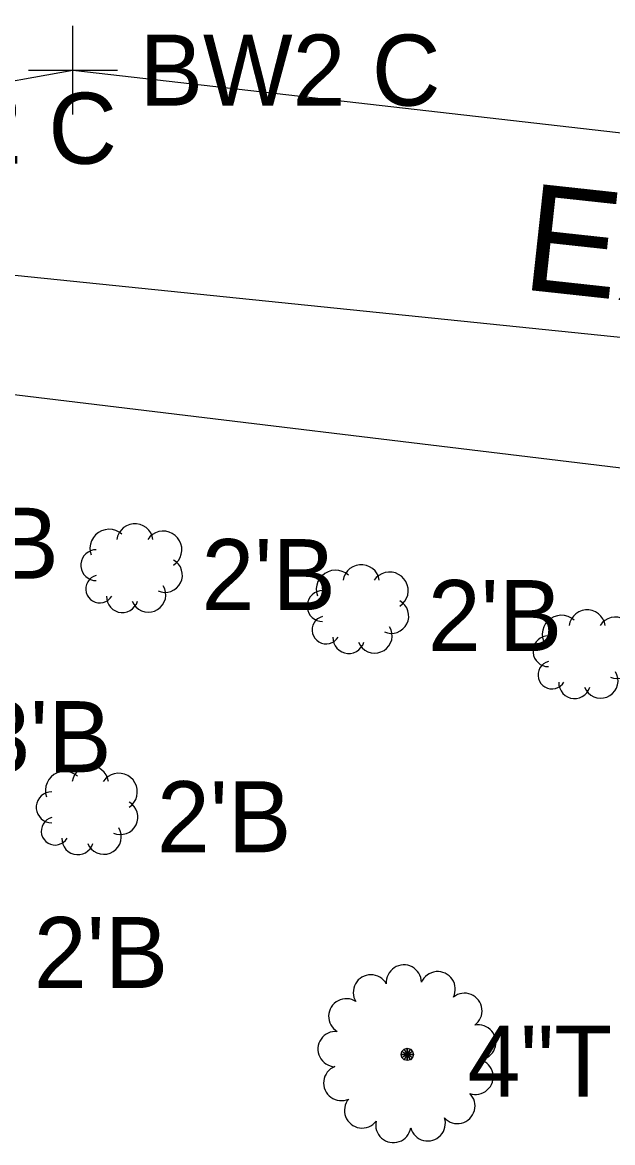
# Model space of a CAD drawing. Extents: x 1363693 to 1365209, y 422201 to 424153.
# Drawn here: x 1364123.23 to 1364136.52, y 423073.16 to 423098.38 of the extents above; entities that cross this region are included whole.
import ezdxf

# ---------------------------------------------------------------- set-up
doc = ezdxf.new("R2010")
doc.units = 0
for name, color, linetype in [('O-ALGN-TEXT-BASELINE-WERK-CL-RW', 7, 'Continuous'), ('SV_X_Shot_Marker', 7, 'Continuous'), ('UT_X_Electric', 7, 'Continuous'), ('UT_X_Electric_Text', 7, 'Continuous'), ('VG_X_Cells', 7, 'Continuous'), ('VG_X_Flower_Bed', 7, 'Continuous'), ('VG_X_Text', 7, 'Continuous')]:
    doc.layers.add(name, color=color, linetype=linetype)

msp = doc.modelspace()

# ---------------------------------------------------------------- linework, layer by layer
at = {"layer": 'O-ALGN-TEXT-BASELINE-WERK-CL-RW'}
msp.add_lwpolyline([(1364082.455, 423089.956), (1364091.492, 423091.463), (1364096.033, 423092.212), (1364096.16, 423092.322), (1364105.9, 423094.014), (1364117.087, 423095.993), (1364124.372, 423097.302), (1364141.98, 423095.292), (1364166.947, 423092.589), (1364178.078, 423091.327), (1364181.068, 423090.938), (1364184.015, 423090.305), (1364184.015, 423090.305), (1364187.51, 423089.214), (1364190.879, 423087.78), (1364190.879, 423087.78), (1364196.807, 423084.458), (1364200.629, 423083.854), (1364205.148, 423082.949)], dxfattribs=at)
at = {"layer": 'SV_X_Shot_Marker'}
for p, q in [((1364124.372, 423096.302), (1364124.372, 423098.302)), ((1364123.372, 423097.302), (1364125.372, 423097.302))]:
    msp.add_line(p, q, dxfattribs=at)
at = {"layer": 'UT_X_Electric'}
msp.add_lwpolyline([(1364201.55, 423074.962), (1364187.938, 423086.039), (1364061.994, 423098.936)], dxfattribs=at)
at = {"layer": 'VG_X_Cells'}
for points in [[(1364125.476, 423086.853), (1364125.411, 423086.902), (1364125.338, 423086.937), (1364125.259, 423086.959), (1364125.177, 423086.965), (1364125.096, 423086.955), (1364125.018, 423086.931), (1364124.947, 423086.892), (1364124.883, 423086.841), (1364124.831, 423086.778), (1364124.791, 423086.707), (1364124.765, 423086.63), (1364124.755, 423086.549), (1364124.76, 423086.467), (1364124.78, 423086.388)], [(1364126.173, 423086.737), (1364126.154, 423086.812), (1364126.122, 423086.883), (1364126.077, 423086.947), (1364126.02, 423087.001), (1364125.955, 423087.043), (1364125.882, 423087.072), (1364125.806, 423087.087), (1364125.727, 423087.087), (1364125.651, 423087.072), (1364125.578, 423087.043), (1364125.513, 423087.001), (1364125.456, 423086.947), (1364125.411, 423086.883), (1364125.378, 423086.812), (1364125.36, 423086.737)], [(1364126.637, 423086.156), (1364126.698, 423086.205), (1364126.748, 423086.264), (1364126.787, 423086.332), (1364126.812, 423086.406), (1364126.823, 423086.482), (1364126.82, 423086.56), (1364126.802, 423086.636), (1364126.771, 423086.707), (1364126.727, 423086.772), (1364126.672, 423086.827), (1364126.608, 423086.87), (1364126.537, 423086.902), (1364126.461, 423086.919), (1364126.383, 423086.922), (1364126.306, 423086.911), (1364126.233, 423086.886), (1364126.165, 423086.847), (1364126.106, 423086.797), (1364126.057, 423086.737)], [(1364124.896, 423086.504), (1364124.832, 423086.498), (1364124.77, 423086.481), (1364124.712, 423086.452), (1364124.661, 423086.413), (1364124.618, 423086.366), (1364124.584, 423086.311), (1364124.561, 423086.251), (1364124.549, 423086.188), (1364124.549, 423086.124), (1364124.561, 423086.061), (1364124.584, 423086.001), (1364124.618, 423085.946), (1364124.661, 423085.899), (1364124.712, 423085.86), (1364124.77, 423085.831), (1364124.832, 423085.814), (1364124.896, 423085.808)], [(1364126.289, 423085.575), (1364126.359, 423085.552), (1364126.433, 423085.542), (1364126.507, 423085.547), (1364126.579, 423085.565), (1364126.646, 423085.597), (1364126.705, 423085.641), (1364126.756, 423085.695), (1364126.795, 423085.758), (1364126.822, 423085.827), (1364126.835, 423085.9), (1364126.834, 423085.974), (1364126.819, 423086.047), (1364126.791, 423086.115), (1364126.75, 423086.177), (1364126.698, 423086.23), (1364126.637, 423086.272)], [(1364131.27, 423085.815), (1364131.251, 423085.89), (1364131.219, 423085.961), (1364131.174, 423086.025), (1364131.117, 423086.079), (1364131.052, 423086.121), (1364130.979, 423086.15), (1364130.903, 423086.165), (1364130.824, 423086.165), (1364130.748, 423086.15), (1364130.675, 423086.121), (1364130.61, 423086.079), (1364130.553, 423086.025), (1364130.508, 423085.961), (1364130.475, 423085.89), (1364130.457, 423085.815)], [(1364124.896, 423085.924), (1364124.838, 423085.903), (1364124.785, 423085.871), (1364124.74, 423085.829), (1364124.704, 423085.779), (1364124.678, 423085.724), (1364124.663, 423085.664), (1364124.661, 423085.603), (1364124.67, 423085.542), (1364124.691, 423085.484), (1364124.723, 423085.432), (1364124.765, 423085.386), (1364124.814, 423085.35), (1364124.87, 423085.324), (1364124.93, 423085.309), (1364124.991, 423085.306), (1364125.052, 423085.316), (1364125.11, 423085.337), (1364125.162, 423085.368), (1364125.208, 423085.41), (1364125.244, 423085.459)], [(1364130.573, 423085.931), (1364130.508, 423085.98), (1364130.435, 423086.015), (1364130.356, 423086.037), (1364130.274, 423086.043), (1364130.193, 423086.033), (1364130.115, 423086.009), (1364130.044, 423085.97), (1364129.98, 423085.919), (1364129.928, 423085.856), (1364129.888, 423085.785), (1364129.862, 423085.708), (1364129.852, 423085.627), (1364129.857, 423085.545), (1364129.877, 423085.466)], [(1364131.734, 423085.234), (1364131.795, 423085.283), (1364131.845, 423085.342), (1364131.884, 423085.41), (1364131.909, 423085.484), (1364131.92, 423085.56), (1364131.917, 423085.638), (1364131.899, 423085.714), (1364131.868, 423085.785), (1364131.824, 423085.85), (1364131.769, 423085.905), (1364131.705, 423085.948), (1364131.634, 423085.98), (1364131.558, 423085.997), (1364131.48, 423086), (1364131.403, 423085.989), (1364131.33, 423085.964), (1364131.262, 423085.925), (1364131.203, 423085.875), (1364131.154, 423085.815)], [(1364125.708, 423085.343), (1364125.743, 423085.276), (1364125.791, 423085.216), (1364125.848, 423085.167), (1364125.915, 423085.13), (1364125.987, 423085.107), (1364126.062, 423085.098), (1364126.138, 423085.103), (1364126.211, 423085.124), (1364126.279, 423085.157), (1364126.339, 423085.204), (1364126.389, 423085.261), (1364126.427, 423085.327), (1364126.452, 423085.399), (1364126.462, 423085.474), (1364126.457, 423085.55), (1364126.438, 423085.623), (1364126.405, 423085.692)], [(1364125.128, 423085.459), (1364125.132, 423085.391), (1364125.149, 423085.325), (1364125.178, 423085.263), (1364125.218, 423085.207), (1364125.269, 423085.161), (1364125.327, 423085.125), (1364125.391, 423085.101), (1364125.459, 423085.09), (1364125.528, 423085.092), (1364125.594, 423085.107), (1364125.657, 423085.134), (1364125.713, 423085.173), (1364125.761, 423085.222), (1364125.799, 423085.28), (1364125.825, 423085.343)], [(1364129.993, 423085.582), (1364129.929, 423085.576), (1364129.867, 423085.559), (1364129.809, 423085.53), (1364129.758, 423085.491), (1364129.715, 423085.444), (1364129.681, 423085.389), (1364129.658, 423085.329), (1364129.646, 423085.266), (1364129.646, 423085.202), (1364129.658, 423085.139), (1364129.681, 423085.079), (1364129.715, 423085.024), (1364129.758, 423084.977), (1364129.809, 423084.938), (1364129.867, 423084.909), (1364129.929, 423084.892), (1364129.993, 423084.886)], [(1364131.386, 423084.653), (1364131.456, 423084.63), (1364131.53, 423084.62), (1364131.604, 423084.625), (1364131.676, 423084.643), (1364131.743, 423084.675), (1364131.802, 423084.719), (1364131.853, 423084.773), (1364131.892, 423084.836), (1364131.919, 423084.905), (1364131.932, 423084.978), (1364131.931, 423085.052), (1364131.916, 423085.125), (1364131.888, 423085.193), (1364131.847, 423085.255), (1364131.795, 423085.308), (1364131.734, 423085.35)], [(1364136.357, 423084.8), (1364136.338, 423084.875), (1364136.306, 423084.946), (1364136.261, 423085.01), (1364136.204, 423085.064), (1364136.139, 423085.106), (1364136.066, 423085.135), (1364135.99, 423085.15), (1364135.911, 423085.15), (1364135.835, 423085.135), (1364135.762, 423085.106), (1364135.697, 423085.064), (1364135.64, 423085.01), (1364135.595, 423084.946), (1364135.562, 423084.875), (1364135.544, 423084.8)], [(1364129.993, 423085.002), (1364129.935, 423084.981), (1364129.882, 423084.949), (1364129.837, 423084.907), (1364129.801, 423084.857), (1364129.775, 423084.802), (1364129.76, 423084.742), (1364129.758, 423084.681), (1364129.767, 423084.62), (1364129.788, 423084.562), (1364129.82, 423084.51), (1364129.862, 423084.464), (1364129.911, 423084.428), (1364129.967, 423084.402), (1364130.027, 423084.387), (1364130.088, 423084.384), (1364130.149, 423084.394), (1364130.207, 423084.415), (1364130.259, 423084.446), (1364130.305, 423084.488), (1364130.341, 423084.537)], [(1364135.66, 423084.916), (1364135.595, 423084.965), (1364135.522, 423085), (1364135.443, 423085.022), (1364135.361, 423085.028), (1364135.28, 423085.018), (1364135.202, 423084.994), (1364135.131, 423084.955), (1364135.067, 423084.904), (1364135.015, 423084.841), (1364134.975, 423084.77), (1364134.949, 423084.693), (1364134.939, 423084.612), (1364134.944, 423084.53), (1364134.964, 423084.451)], [(1364136.821, 423084.219), (1364136.882, 423084.268), (1364136.932, 423084.327), (1364136.971, 423084.395), (1364136.996, 423084.469), (1364137.007, 423084.545), (1364137.004, 423084.623), (1364136.986, 423084.699), (1364136.955, 423084.77), (1364136.911, 423084.835), (1364136.856, 423084.89), (1364136.792, 423084.933), (1364136.721, 423084.965), (1364136.645, 423084.982), (1364136.567, 423084.985), (1364136.49, 423084.974), (1364136.417, 423084.949), (1364136.349, 423084.91), (1364136.29, 423084.86), (1364136.241, 423084.8)], [(1364130.805, 423084.421), (1364130.84, 423084.354), (1364130.888, 423084.294), (1364130.945, 423084.245), (1364131.012, 423084.208), (1364131.084, 423084.185), (1364131.159, 423084.176), (1364131.235, 423084.181), (1364131.308, 423084.202), (1364131.376, 423084.235), (1364131.436, 423084.282), (1364131.486, 423084.339), (1364131.524, 423084.405), (1364131.549, 423084.477), (1364131.559, 423084.552), (1364131.554, 423084.628), (1364131.535, 423084.701), (1364131.502, 423084.77)], [(1364130.225, 423084.537), (1364130.229, 423084.469), (1364130.246, 423084.403), (1364130.275, 423084.341), (1364130.315, 423084.285), (1364130.366, 423084.239), (1364130.424, 423084.203), (1364130.488, 423084.179), (1364130.556, 423084.168), (1364130.625, 423084.17), (1364130.691, 423084.185), (1364130.754, 423084.212), (1364130.81, 423084.251), (1364130.858, 423084.3), (1364130.896, 423084.358), (1364130.922, 423084.421)], [(1364135.08, 423084.567), (1364135.016, 423084.561), (1364134.954, 423084.544), (1364134.896, 423084.515), (1364134.845, 423084.476), (1364134.802, 423084.429), (1364134.768, 423084.374), (1364134.745, 423084.314), (1364134.733, 423084.251), (1364134.733, 423084.187), (1364134.745, 423084.124), (1364134.768, 423084.064), (1364134.802, 423084.009), (1364134.845, 423083.962), (1364134.896, 423083.923), (1364134.954, 423083.894), (1364135.016, 423083.877), (1364135.08, 423083.871)], [(1364136.473, 423083.638), (1364136.543, 423083.615), (1364136.617, 423083.605), (1364136.691, 423083.61), (1364136.763, 423083.628), (1364136.83, 423083.66), (1364136.889, 423083.704), (1364136.94, 423083.758), (1364136.979, 423083.821), (1364137.006, 423083.89), (1364137.019, 423083.963), (1364137.018, 423084.037), (1364137.003, 423084.11), (1364136.975, 423084.178), (1364136.934, 423084.24), (1364136.882, 423084.293), (1364136.821, 423084.335)], [(1364135.08, 423083.987), (1364135.022, 423083.966), (1364134.969, 423083.934), (1364134.924, 423083.892), (1364134.888, 423083.842), (1364134.862, 423083.787), (1364134.847, 423083.727), (1364134.845, 423083.666), (1364134.854, 423083.605), (1364134.875, 423083.547), (1364134.907, 423083.495), (1364134.949, 423083.449), (1364134.998, 423083.413), (1364135.054, 423083.387), (1364135.114, 423083.372), (1364135.175, 423083.369), (1364135.236, 423083.379), (1364135.294, 423083.4), (1364135.346, 423083.431), (1364135.392, 423083.473), (1364135.428, 423083.522)], [(1364135.892, 423083.406), (1364135.927, 423083.339), (1364135.975, 423083.279), (1364136.032, 423083.23), (1364136.099, 423083.193), (1364136.171, 423083.17), (1364136.246, 423083.161), (1364136.322, 423083.166), (1364136.395, 423083.187), (1364136.463, 423083.22), (1364136.523, 423083.267), (1364136.573, 423083.324), (1364136.611, 423083.39), (1364136.636, 423083.462), (1364136.646, 423083.537), (1364136.641, 423083.613), (1364136.622, 423083.686), (1364136.589, 423083.755)], [(1364135.312, 423083.522), (1364135.316, 423083.454), (1364135.333, 423083.388), (1364135.362, 423083.326), (1364135.402, 423083.27), (1364135.453, 423083.224), (1364135.511, 423083.188), (1364135.575, 423083.164), (1364135.643, 423083.153), (1364135.712, 423083.155), (1364135.778, 423083.17), (1364135.841, 423083.197), (1364135.897, 423083.236), (1364135.945, 423083.285), (1364135.983, 423083.343), (1364136.009, 423083.406)], [(1364125.17, 423081.286), (1364125.151, 423081.361), (1364125.119, 423081.432), (1364125.074, 423081.496), (1364125.017, 423081.55), (1364124.952, 423081.592), (1364124.879, 423081.621), (1364124.803, 423081.636), (1364124.724, 423081.636), (1364124.648, 423081.621), (1364124.575, 423081.592), (1364124.51, 423081.55), (1364124.453, 423081.496), (1364124.408, 423081.432), (1364124.375, 423081.361), (1364124.357, 423081.286)], [(1364124.473, 423081.402), (1364124.408, 423081.451), (1364124.335, 423081.486), (1364124.256, 423081.508), (1364124.174, 423081.514), (1364124.093, 423081.504), (1364124.015, 423081.48), (1364123.944, 423081.441), (1364123.88, 423081.39), (1364123.828, 423081.327), (1364123.788, 423081.256), (1364123.762, 423081.179), (1364123.752, 423081.098), (1364123.757, 423081.016), (1364123.777, 423080.937)], [(1364125.634, 423080.705), (1364125.695, 423080.754), (1364125.745, 423080.813), (1364125.784, 423080.881), (1364125.809, 423080.955), (1364125.82, 423081.031), (1364125.817, 423081.109), (1364125.799, 423081.185), (1364125.768, 423081.256), (1364125.724, 423081.321), (1364125.669, 423081.376), (1364125.605, 423081.419), (1364125.534, 423081.451), (1364125.458, 423081.468), (1364125.38, 423081.471), (1364125.303, 423081.46), (1364125.23, 423081.435), (1364125.162, 423081.396), (1364125.103, 423081.346), (1364125.054, 423081.286)], [(1364123.893, 423081.053), (1364123.829, 423081.047), (1364123.767, 423081.03), (1364123.709, 423081.001), (1364123.658, 423080.962), (1364123.615, 423080.915), (1364123.581, 423080.86), (1364123.558, 423080.8), (1364123.546, 423080.737), (1364123.546, 423080.673), (1364123.558, 423080.61), (1364123.581, 423080.55), (1364123.615, 423080.495), (1364123.658, 423080.448), (1364123.709, 423080.409), (1364123.767, 423080.38), (1364123.829, 423080.363), (1364123.893, 423080.357)], [(1364125.286, 423080.124), (1364125.356, 423080.101), (1364125.43, 423080.091), (1364125.504, 423080.096), (1364125.576, 423080.114), (1364125.643, 423080.146), (1364125.702, 423080.19), (1364125.753, 423080.244), (1364125.792, 423080.307), (1364125.819, 423080.376), (1364125.832, 423080.449), (1364125.831, 423080.523), (1364125.816, 423080.596), (1364125.788, 423080.664), (1364125.747, 423080.726), (1364125.695, 423080.779), (1364125.634, 423080.821)], [(1364123.893, 423080.473), (1364123.835, 423080.452), (1364123.782, 423080.42), (1364123.737, 423080.378), (1364123.701, 423080.328), (1364123.675, 423080.273), (1364123.66, 423080.213), (1364123.658, 423080.152), (1364123.667, 423080.091), (1364123.688, 423080.033), (1364123.72, 423079.981), (1364123.762, 423079.935), (1364123.811, 423079.899), (1364123.867, 423079.873), (1364123.927, 423079.858), (1364123.988, 423079.855), (1364124.049, 423079.865), (1364124.107, 423079.886), (1364124.159, 423079.917), (1364124.205, 423079.959), (1364124.241, 423080.008)], [(1364124.705, 423079.892), (1364124.74, 423079.825), (1364124.788, 423079.765), (1364124.845, 423079.716), (1364124.912, 423079.679), (1364124.984, 423079.656), (1364125.059, 423079.647), (1364125.135, 423079.652), (1364125.208, 423079.673), (1364125.276, 423079.706), (1364125.336, 423079.753), (1364125.386, 423079.81), (1364125.424, 423079.876), (1364125.449, 423079.948), (1364125.459, 423080.023), (1364125.454, 423080.099), (1364125.435, 423080.172), (1364125.402, 423080.241)], [(1364124.125, 423080.008), (1364124.129, 423079.94), (1364124.146, 423079.874), (1364124.175, 423079.812), (1364124.215, 423079.756), (1364124.266, 423079.71), (1364124.324, 423079.674), (1364124.388, 423079.65), (1364124.456, 423079.639), (1364124.525, 423079.641), (1364124.591, 423079.656), (1364124.654, 423079.683), (1364124.71, 423079.722), (1364124.758, 423079.771), (1364124.796, 423079.829), (1364124.822, 423079.892)]]:
    msp.add_lwpolyline(points, dxfattribs=at)
for points in [[(1364131.831, 423075.26), (1364131.9, 423075.141), (1364131.9, 423075.141), (1364131.781, 423075.21)], [(1364131.9, 423075.278), (1364131.9, 423075.141), (1364131.9, 423075.141), (1364131.831, 423075.26)], [(1364131.969, 423075.26), (1364131.9, 423075.141), (1364131.9, 423075.141), (1364131.9, 423075.278)], [(1364132.019, 423075.21), (1364131.9, 423075.141), (1364131.9, 423075.141), (1364131.969, 423075.26)], [(1364131.781, 423075.21), (1364131.9, 423075.141), (1364131.9, 423075.141), (1364131.763, 423075.141)], [(1364131.763, 423075.141), (1364131.9, 423075.141), (1364131.9, 423075.141), (1364131.781, 423075.072)], [(1364131.781, 423075.072), (1364131.9, 423075.141), (1364131.9, 423075.141), (1364131.831, 423075.022)], [(1364131.831, 423075.022), (1364131.9, 423075.141), (1364131.9, 423075.141), (1364131.9, 423075.004)], [(1364132.037, 423075.141), (1364131.9, 423075.141), (1364131.9, 423075.141), (1364132.019, 423075.21)], [(1364131.9, 423075.004), (1364131.9, 423075.141), (1364131.9, 423075.141), (1364131.969, 423075.022)], [(1364131.969, 423075.022), (1364131.9, 423075.141), (1364131.9, 423075.141), (1364132.019, 423075.072)], [(1364132.019, 423075.072), (1364131.9, 423075.141), (1364131.9, 423075.141), (1364132.037, 423075.141)]]:
    msp.add_lwpolyline(points, close=True, dxfattribs=at)
for centre, start, end in [((1364131.824, 423076.759), 1.241, 184.1237), ((1364131.081, 423076.538), 28.9333, 211.816), ((1364132.585, 423076.609), 333.5487, 156.4314), ((1364133.188, 423076.122), 305.8564, 128.7391), ((1364130.526, 423075.998), 56.6256, 239.5083), ((1364133.497, 423075.411), 278.1641, 101.0468), ((1364130.285, 423075.261), 84.3179, 267.2006), ((1364133.439, 423074.638), 250.4718, 73.3545), ((1364130.414, 423074.497), 112.0103, 294.8929), ((1364133.029, 423073.98), 222.7795, 45.6622), ((1364130.884, 423073.88), 139.7026, 322.5852), ((1364131.586, 423073.552), 167.3949, 350.2776), ((1364132.361, 423073.589), 195.0872, 17.9699)]:
    msp.add_arc(centre, 0.397, start, end, dxfattribs=at)
at = {"layer": 'VG_X_Flower_Bed'}
msp.add_line((1364116.472, 423090.791), (1364140.968, 423087.835), dxfattribs=at)

# ---------------------------------------------------------------- texts
at = {"layer": 'SV_X_Shot_Marker'}
for p in [(1364125.872, 423096.502), (1364118.587, 423095.193)]:
    msp.add_text('BW2 C', height=1.6, dxfattribs=at).set_placement(p)
at = {"layer": 'UT_X_Electric_Text'}
msp.add_text('EX. ELECTRIC', height=2.4, rotation=353.8006, dxfattribs=at).set_placement((1364134.446, 423092.371))
at = {"layer": 'VG_X_Text'}
for s, p in [("2'B", (1364121.027, 423085.85)), ("2'B", (1364127.266, 423085.143)), ("2'B", (1364132.363, 423084.221)), ("3'B", (1364122.215, 423081.494)), ("2'B", (1364126.263, 423079.692)), ("2'B", (1364123.49, 423076.635)), ('4"T', (1364133.257, 423074.189))]:
    msp.add_text(s, height=1.6, dxfattribs=at).set_placement(p)

doc.saveas('drawing.dxf')
